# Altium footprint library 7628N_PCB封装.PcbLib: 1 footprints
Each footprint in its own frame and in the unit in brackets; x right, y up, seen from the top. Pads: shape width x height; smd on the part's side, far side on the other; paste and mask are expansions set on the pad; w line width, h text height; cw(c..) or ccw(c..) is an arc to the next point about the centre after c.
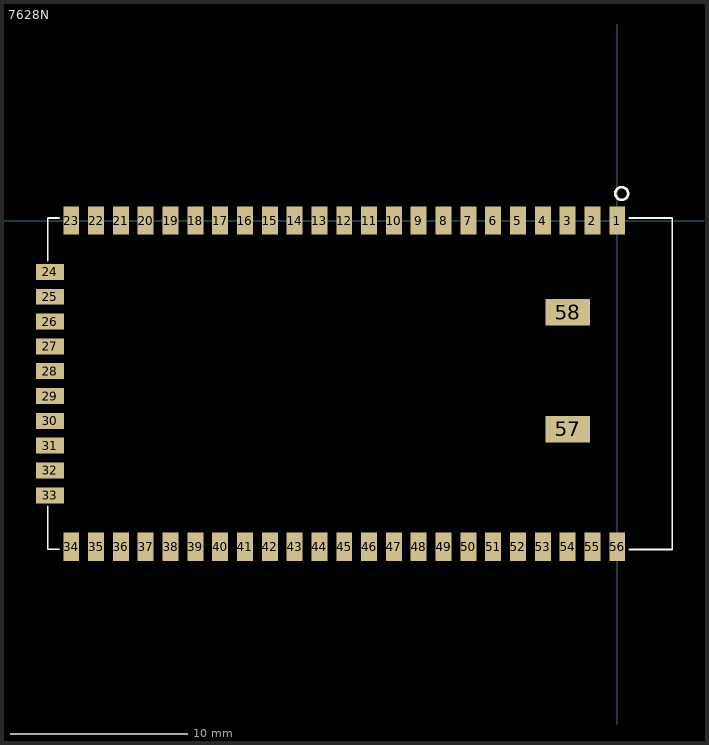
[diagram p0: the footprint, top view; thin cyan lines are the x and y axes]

## 7628N [mm]
height 2.5
pads (58):
  rect 0.9x1.6 smd: 1(0,0) 2(-1.4,0) 3(-2.8,0) 4(-4.2,0) 5(-5.6,0) 6(-7,0) 7(-8.4,0) 8(-9.8,0) 9(-11.2,0) 10(-12.6,0) 11(-14,0) 12(-15.4,0) 13(-16.8,0) 14(-18.2,0) 15(-19.6,0) 16(-21,0) 17(-22.4,0) 18(-23.8,0) 19(-25.2,0) 20(-26.6,0) 21(-28,0) 22(-29.4,0) 23(-30.8,0) 34(-30.8,-18.4) 35(-29.4,-18.4) 36(-28,-18.4) 37(-26.6,-18.4) 38(-25.2,-18.4) 39(-23.8,-18.4) 40(-22.4,-18.4) 41(-21,-18.4) 42(-19.6,-18.4) 43(-18.2,-18.4) 44(-16.8,-18.4) 45(-15.4,-18.4) 46(-14,-18.4) 47(-12.6,-18.4) 48(-11.2,-18.4) 49(-9.8,-18.4) 50(-8.4,-18.4) 51(-7,-18.4) 52(-5.6,-18.4) 53(-4.2,-18.4) 54(-2.8,-18.4) 55(-1.4,-18.4) 56(0,-18.4)
  rect 1.6x0.9 smd: 24(-32,-2.9) 25(-32,-4.3) 26(-32,-5.7) 27(-32,-7.1) 28(-32,-8.5) 29(-32,-9.9) 30(-32,-11.3) 31(-32,-12.7) 32(-32,-14.1) 33(-32,-15.5)
  rect 2.5x1.5 smd: 57(-2.8,-11.773) 58(-2.8,-5.173)
Top Layer:
  lines w0.15: -30.8,-18.4 -30.8,-18.4
Top Overlay:
  circle w0.15: c0.254,1.524 r0.359
  lines w0.1: -32.131,-16.129 -32.131,-18.542 -31.496,-18.542 ; -32.131,-2.271 -32.131,0.142 -31.496,0.142 ; 0.696,-18.557 3.1,-18.557 3.1,0.142 0.696,0.142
